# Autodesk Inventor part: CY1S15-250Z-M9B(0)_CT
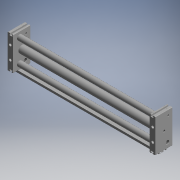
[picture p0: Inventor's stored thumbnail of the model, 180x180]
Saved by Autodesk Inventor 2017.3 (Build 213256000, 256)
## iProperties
Part Number: CY1S15-250Z-M9B(0)_CT
Material: Generic
Catalog Web Link: www.cadenas.de
Description: CY1S-Z_CT-Magnetically Coupled Rodless Cylinder Slider Type/Slide Bearing
Vendor: SMC
Document SubType Name: Modeling
Designer: partserver
Manufacturer: SMC
Mass: 219.448 g
Surface Area: 857.61 cm^2
Volume: 219.448 cm^3
Density: 1 g/cm^3
Appearance: PSOLRGB-192-192-192
Category: PARTsolutions
Company: SMC
Title: CY1S15-250Z-M9B_CT
Author: Cadenas PARTsolutions
Comments: Magnetically Coupled Rodless Cylinder Slider Type/Slide Bearing
PSOL_IDENT_0: {$CADENAS_DATA\23d-libs\smc_jp\actuator\rodless_cylinders\cy1\cy1s_z\parts\cy1s_z_cylinder_tube.prj}
PSOL_IDENT_1: ,233 {VTYP=3D},{NB=CY1S15-250Z-M9B(0)_CT},{LINA=CY1S15-250Z-M9B_CT},{NN=CY1S-Z_CT},{DATE=09.12.2020
PSOL_IDENT_2: 02:54:14},{GEOMDATE=09.03.2020 08:58:35},{VERSION=},{LINEID=30},{WBVAR=PIPING,STROKE,STOPPER,AUTOSWI
PSOL_IDENT_3: TCH,OMSC,THREAD2},{WBNUMERIC=STROKE}  {NB=CY1S15-250Z-M9B(0)_CT},{LINA=CY1S15-250Z-M9B_CT},{KT=DUMMY
PSOL_IDENT_4: },{BORE=15},{PIPING=},{STROKE=250},{STOPPER=},{AUTOSWITCH=-M9B},{OMSC=},{THREAD2=0},{STDSTROKE=50,10
PSOL_IDENT_5: 0,150,200,250,300,350,400,450,500},{SMIN=25},{SMAX=750.000},{ORDER=CY1S15-250Z-M9B},{A=7.5},{B=9.5},
PSOL_IDENT_6: {C=5.4},{D=16.6},{D1=12},{G=6.5},{GA=5.000},{GB=6},{GP=52},{H=40},{HA=28.0},{HB=29.5},{HC=20.500},{H
PSOL_IDENT_7: G=15.000},{HP=39},{HT=20.500},{JJ=M4x0.7},{JJRA=4.000},{JJRP=0.700},{JJD=5.000},{K=11.0},{L=60},{LD=
PSOL_IDENT_8: 5.8},{M=8},{MM=M5x0.8},{NA=10.5},{NB1=16.5},{NC=28.0},{NN=M4x0.7},{P=M5x0.8},{PRA=5.000},{PRP=0.800}
PSOL_IDENT_9: ,{PRD=6.000},{PA=30},{PB=50},{PW=76},{Q=75},{QW=30},{R=1.000},{R1=5.500},{S=62},{T=12.5},{TT=17.500}
PSOL_IDENT_10: ,{UU=M8x1},{UURA=8.000},{UURD=1.000},{W=72},{Y1=14.0},{Z=87},{A1=7.500},{A2=3.400},{A3=5.800},{B1=3.
PSOL_IDENT_11: 500},{B2=11.000},{B3=7.500},{B4=80.000},{J=M6x1},{JRA=6.000},{JRP=1.000},{RR=9.500},{C1=39.000},{POS=
PSOL_IDENT_12: MIN},{STOP=MIN}
NB: CY1S15-250Z-M9B(0)_CT
NN: M4x0.7
NT: Magnetically Coupled Rodless Cylinder Slider Type/Slide Bearing
NBSYN: $ORDER.($THREAD2.)_CT
LINA: CY1S15-250Z-M9B_CT
CATALOG: SMC (JP
BORE: 15
PIPING: (-) Bilateral piping type
STROKE: 250
STOPPER: (-) Bumper bolt (resin tipped):Mounted on both sides
AUTOSWITCH: M9B
OMSC: (-) None
THREAD2: on
STDSTROKE: 50,100,150,200,250,300,350,400,450,500
SMIN: 25
SMAX: 750
A: 7.5
B: 9.5
C: 5.4
D: 16.6
D1: 12
G: 6.5
GA: 5
GB: 6
GP: 52
H: 40
HA: 28
HB: 29.5
HC: 20.5
HG: 15
HP: 39
HT: 20.5
JJ: M4x0.7
JJRA: 4
JJRP: 0.7
JJD: 5
K: 11
L: 60
LD: 5.8
M: 8
MM: M5x0.8
NA: 10.5
NB1: 16.5
NC: 28
P: M5x0.8
PRA: 5
PRP: 0.8
PRD: 6
PA: 30
PB: 50
PW: 76
Q: 75
QW: 30
R: 1
R1: 5.5
S: 62
T: 12.5
TT: 17.5
UU: M8x1
UURA: 8
UURD: 1
W: 72
Y1: 14
Z: 87
A1: 7.5
A2: 3.4
A3: 5.8
B1: 3.5
B2: 11
B3: 7.5
B4: 80
J: M6x1
JRA: 6
JRP: 1
RR: 9.5
C1: 39
POS: 0
STOP: 0
SUPPLIER: SMC
ARTICLENO: CY1S15-250Z-M9B(0)_CT
BOMINFO: CY1S15-250Z-M9B_CT
CREATOR: CADENAS GmbH
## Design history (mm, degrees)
sketch "Sketch_1"
  geometry: L1 (6, -37)-(6, 37); L2 (5, 38)-(0.25, 38); L3 (0.25, 38)-(0.25, 36.1); L4 (0.25, 36.1)-(1.5, 36.1); L5 (1.5, 36.1)-(1.5, 33.4); L6 (1.5, 33.4)-(-4.5, 33.4); L7 (-4.5, 33.4)-(-4.5, 36.1); L8 (-4.5, 36.1)-(-3.25, 36.1); L9 (-3.25, 36.1)-(-3.25, 38); L10 (-3.25, 38)-(-5.5, 38); L11 (-6.5, 37)-(-6.5, -37); L12 (-5.5, -38)-(-3.25, -38); L13 (-3.25, -38)-(-3.25, -36.1); L14 (-3.25, -36.1)-(-4.5, -36.1); L15 (-4.5, -36.1)-(-4.5, -33.4); L16 (-4.5, -33.4)-(1.5, -33.4); L17 (1.5, -33.4)-(1.5, -36.1); L18 (1.5, -36.1)-(0.25, -36.1); L19 (0.25, -36.1)-(0.25, -38); L20 (0.25, -38)-(5, -38); A1 r 1 centre (5, 37) between (6, 37) and (5, 38); A2 r 1 centre (-5.5, 37) between (-5.5, 38) and (-6.5, 37); A3 r 1 centre (-5.5, -37) between (-6.5, -37) and (-5.5, -38); A4 r 1 centre (5, -37) between (5, -38) and (6, -37)
  constraints: 40 end point, 8 point on circle, 4 centre point
extrude "Extrusion1" join sketch "Sketch_1" distance "d0" = 39; taper "d1" = 0 deg
sketch "Sketch_2"
  geometry: C1 r 8.3 at (0, 20.5); 1 further point
  constraints: 1 centre point
extrude "Extrusion2" join sketch "Sketch_2" distance "d2" = 312; taper "d3" = 0 deg
sketch "Sketch_3"
  geometry: C1 r 6 at (26, 15); 1 further point
  constraints: 1 centre point
extrude "Extrusion3" join sketch "Sketch_3" distance "d4" = 312; taper "d5" = 0 deg
sketch "Sketch_4"
  geometry: C1 r 6 at (-26, 15); 1 further point
  constraints: 1 centre point
extrude "Extrusion4" join sketch "Sketch_4" distance "d6" = 312; taper "d7" = 0 deg
sketch "Sketch_5"
  geometry: L1 (-318.5, -37)-(-318.5, 37); L2 (-319.5, 38)-(-321.75, 38); L3 (-321.75, 38)-(-321.75, 36.1); L4 (-321.75, 36.1)-(-320.5, 36.1); L5 (-320.5, 36.1)-(-320.5, 33.4); L6 (-320.5, 33.4)-(-326.5, 33.4); L7 (-326.5, 33.4)-(-326.5, 36.1); L8 (-326.5, 36.1)-(-325.25, 36.1); L9 (-325.25, 36.1)-(-325.25, 38); L10 (-325.25, 38)-(-330, 38); L11 (-331, 37)-(-331, -37); L12 (-330, -38)-(-325.25, -38); L13 (-325.25, -38)-(-325.25, -36.1); L14 (-325.25, -36.1)-(-326.5, -36.1); L15 (-326.5, -36.1)-(-326.5, -33.4); L16 (-326.5, -33.4)-(-320.5, -33.4); L17 (-320.5, -33.4)-(-320.5, -36.1); L18 (-320.5, -36.1)-(-321.75, -36.1); L19 (-321.75, -36.1)-(-321.75, -38); L20 (-321.75, -38)-(-319.5, -38); A1 r 1 centre (-319.5, 37) between (-318.5, 37) and (-319.5, 38); A2 r 1 centre (-330, 37) between (-330, 38) and (-331, 37); A3 r 1 centre (-330, -37) between (-331, -37) and (-330, -38); A4 r 1 centre (-319.5, -37) between (-319.5, -38) and (-318.5, -37)
  constraints: 40 end point, 8 point on circle, 4 centre point
extrude "Extrusion5" join sketch "Sketch_5" distance "d8" = 39; taper "d9" = 0 deg
sketch "Sketch_45"
  geometry: L1 (-39.8, 41)-(-39.8, 9); L2 (-39.8, 9)-(-37.8, 11); L3 (-37.8, 11)-(-37.8, 30); L4 (-37.8, 30)-(-38, 30.2); L5 (-38, 30.2)-(-38, 39); L6 (-38, 39)-(38, 39); L7 (38, 39)-(38, 30.2); L8 (38, 30.2)-(37.8, 30); L9 (37.8, 30)-(37.8, 11); L10 (37.8, 11)-(39.8, 9); L11 (39.8, 9)-(39.8, 41); L12 (39.8, 41)-(-39.8, 41)
  constraints: 24 end point
extrude "Extrusion6" cut sketch "Sketch_45" distance "d10" = 353.5; taper "d11" = 0 deg
sketch "Sketch7"
  geometry: 1 further point
hole "Hole1" sketch "Sketch7" at (0, -15) diameter "d12" = 5.8; stored, may be unused: countersink angle "d16" = 90 deg, drill point angle "d18" = 0 deg; dims "d13" = 6, "d14" = 9.5, "d15" = 5.4, "d17" = 39
pattern_linear "Rectangular Pattern1" dims "d21" = 325, "d24" = 30
sketch "Sketch_8"
  geometry: L1 (-6, 29.5)-(6.5, 29.5); L2 (6.5, 29.5)-(6.5, 27.5); L3 (6.5, 27.5)-(6.121, 27.879); L4 (6.121, 27.879)-(-5.621, 27.879); L5 (-5.621, 27.879)-(-6, 27.5); L6 (-6, 27.5)-(-6, 29.5); L7 (-6, 29.5)-(6.5, 29.5)
  constraints: 14 end point
revolve "Revolution1" sketch "Sketch_8" stored, may be unused: angle "d25" = 360 deg
thread "Thread1" dims "d26" = 11.742, "d27" = 0
sketch "Sketch_9"
  geometry: L1 (318.5, 29.5)-(331, 29.5); L2 (331, 29.5)-(331, 27.5); L3 (331, 27.5)-(330.621, 27.879); L4 (330.621, 27.879)-(318.879, 27.879); L5 (318.879, 27.879)-(318.5, 27.5); L6 (318.5, 27.5)-(318.5, 29.5); L7 (318.5, 29.5)-(331, 29.5)
  constraints: 14 end point
revolve "Revolution2" sketch "Sketch_9" stored, may be unused: angle "d28" = 360 deg
thread "Thread2" dims "d29" = 11.742, "d30" = 0
sketch "Sketch_12"
  geometry: L1 (-6, 28)-(6.5, 28); L2 (6.5, 28)-(6.5, 24); L3 (6.5, 24)-(5.958, 24.542); L4 (5.958, 24.542)-(-5.459, 24.542); L5 (-5.459, 24.542)-(-6, 24); L6 (-6, 24)-(-6, 28); L7 (-6, 28)-(6.5, 28)
  constraints: 14 end point
revolve "Revolution3" sketch "Sketch_12" stored, may be unused: angle "d31" = 360 deg
thread "Thread3" dims "d32" = 11.417, "d33" = 0
sketch "Sketch_13"
  geometry: L1 (318.5, 28)-(331, 28); L2 (331, 28)-(331, 24); L3 (331, 24)-(330.459, 24.542); L4 (330.459, 24.542)-(319.042, 24.542); L5 (319.042, 24.542)-(318.5, 24); L6 (318.5, 24)-(318.5, 28); L7 (318.5, 28)-(331, 28)
  constraints: 14 end point
revolve "Revolution4" sketch "Sketch_13" stored, may be unused: angle "d34" = 360 deg
thread "Thread4" dims "d35" = 11.417, "d36" = 0
sketch "Sketch_16"
  geometry: L1 (1.193, 20.5)-(-6, 20.5); L2 (-6, 20.5)-(-6, 23); L3 (-6, 23)-(-5.567, 22.567); L4 (-5.567, 22.567)-(0, 22.567); L5 (0, 22.567)-(1.193, 20.5); L6 (1.193, 20.5)-(-6, 20.5)
  constraints: 12 end point
revolve "Revolution5" sketch "Sketch_16" stored, may be unused: angle "d37" = 360 deg
thread "Thread5" dims "d38" = 5.567, "d39" = 0
sketch "Sketch_17"
  geometry: L1 (331, 20.5)-(323.807, 20.5); L2 (323.807, 20.5)-(325, 22.567); L3 (325, 22.567)-(330.567, 22.567); L4 (330.567, 22.567)-(331, 23); L5 (331, 23)-(331, 20.5); L6 (331, 20.5)-(323.807, 20.5)
  constraints: 12 end point
revolve "Revolution6" sketch "Sketch_17" stored, may be unused: angle "d40" = 360 deg
thread "Thread6" dims "d41" = 5.567, "d42" = 0
sketch "Sketch_22"
  geometry: L1 (1.5, -41.9)-(1.5, -33.7); L2 (1.5, -33.7)-(4.25, -33.7); L3 (4.25, -33.7)-(4.25, -36.1); L4 (4.25, -36.1)-(3, -36.1); L5 (3, -36.1)-(3, -39.2); L6 (3, -39.2)-(4.45, -39.2); L7 (4.45, -39.2)-(4.45, -39.9); L8 (4.45, -39.9)-(4.25, -39.9); L9 (4.25, -39.9)-(4.25, -40.9); L10 (3.25, -41.9)-(1.5, -41.9); L11 (1.5, -41.9)-(1.5, -33.7); A1 r 1 centre (3.25, -40.9) between (3.25, -41.9) and (4.25, -40.9)
  constraints: 22 end point, 2 point on circle, 1 centre point
revolve "Revolution7" sketch "Sketch_22" stored, may be unused: angle "d43" = 360 deg
sketch "Sketch_24"
  geometry: L1 (323.5, -41.9)-(323.5, -33.7); L2 (323.5, -33.7)-(326.25, -33.7); L3 (326.25, -33.7)-(326.25, -36.1); L4 (326.25, -36.1)-(325, -36.1); L5 (325, -36.1)-(325, -39.2); L6 (325, -39.2)-(326.45, -39.2); L7 (326.45, -39.2)-(326.45, -39.9); L8 (326.45, -39.9)-(326.25, -39.9); L9 (326.25, -39.9)-(326.25, -40.9); L10 (325.25, -41.9)-(323.5, -41.9); L11 (323.5, -41.9)-(323.5, -33.7); A1 r 1 centre (325.25, -40.9) between (325.25, -41.9) and (326.25, -40.9)
  constraints: 22 end point, 2 point on circle, 1 centre point
revolve "Revolution8" sketch "Sketch_24" stored, may be unused: angle "d44" = 360 deg
sketch "Sketch_23"
  geometry: L1 (-43.4, 28.5)-(-43.4, 27.5); L2 (-43.4, 27.5)-(-42.658, 27.5); L3 (-38.8, 27.04)-(-38.8, 22.96); L4 (-42.658, 22.5)-(-43.4, 22.5); L5 (-43.4, 22.5)-(-43.4, 18.8); L6 (-43.1, 18.5)-(-42.6, 18.5); L7 (-42.3, 18.8)-(-42.3, 19.5); L8 (-41.3, 20.5)-(-39.5, 20.5); L9 (-39.2, 20.2)-(-39.2, 13.3); L10 (-39.5, 13)-(-41.3, 13); L11 (-42.3, 14)-(-42.3, 15.2); L12 (-42.6, 15.5)-(-43.1, 15.5); L13 (-43.4, 15.2)-(-43.4, 12); L14 (-42.4, 11)-(-37.8, 11); L15 (-37.8, 11)-(-37.8, 29.5); L16 (-37.8, 29.5)-(-42.4, 29.5); A1 r 3 centre (-41, 25) between (-38.8, 27.04) and (-42.658, 27.5); A2 r 3 centre (-41, 25) between (-42.658, 22.5) and (-38.8, 22.96); A3 r 0.3 centre (-43.1, 18.8) between (-43.4, 18.8) and (-43.1, 18.5); A4 r 0.3 centre (-42.6, 18.8) between (-42.6, 18.5) and (-42.3, 18.8); A5 r 1 centre (-41.3, 19.5) between (-41.3, 20.5) and (-42.3, 19.5); A6 r 0.3 centre (-39.5, 20.2) between (-39.2, 20.2) and (-39.5, 20.5); A7 r 0.3 centre (-39.5, 13.3) between (-39.5, 13) and (-39.2, 13.3); A8 r 1 centre (-41.3, 14) between (-42.3, 14) and (-41.3, 13); A9 r 0.3 centre (-42.6, 15.2) between (-42.3, 15.2) and (-42.6, 15.5); A10 r 0.3 centre (-43.1, 15.2) between (-43.1, 15.5) and (-43.4, 15.2); A11 r 1 centre (-42.4, 12) between (-43.4, 12) and (-42.4, 11); A12 r 1 centre (-42.4, 28.5) between (-42.4, 29.5) and (-43.4, 28.5)
  constraints: 32 end point, 24 point on circle, 12 centre point
extrude "Extrusion7" join sketch "Sketch_23" distance "d45" = 330; taper "d46" = 0 deg
node "CT_BODY_XY"
node "CT_BODY_YZ"
node "CT_BODY_ZX"
node "CT_BODY_X"
node "CT_BODY_Y"
node "CT_BODY_Z"
node "CT_BODY_Center"
node "CT_DUMMY_XY"
node "CT_DUMMY_YZ"
node "CT_DUMMY_ZX"
node "CT_DUMMY_X"
node "CT_DUMMY_Y"
node "CT_DUMMY_Z"
node "CT_DUMMY_Center"
node "CT_SMA1_XY"
node "CT_SMA1_YZ"
node "CT_SMA1_ZX"
node "CT_SMA1_X"
node "CT_SMA1_Y"
node "CT_SMA1_Z"
node "CT_SMA1_Center"
node "CT_SMA2_XY"
node "CT_SMA2_YZ"
node "CT_SMA2_ZX"
node "CT_SMA2_X"
node "CT_SMA2_Y"
node "CT_SMA2_Z"
node "CT_SMA2_Center"
node "CT_SMB1_XY"
node "CT_SMB1_YZ"
node "CT_SMB1_ZX"
node "CT_SMB1_X"
node "CT_SMB1_Y"
node "CT_SMB1_Z"
node "CT_SMB1_Center"
node "CT_STOPPER1_XY"
node "CT_STOPPER1_YZ"
node "CT_STOPPER1_ZX"
node "CT_STOPPER1_X"
node "CT_STOPPER1_Y"
node "CT_STOPPER1_Z"
node "CT_STOPPER1_Center"
node "CT_STOPPER2_XY"
node "CT_STOPPER2_YZ"
node "CT_STOPPER2_ZX"
node "CT_STOPPER2_X"
node "CT_STOPPER2_Y"
node "CT_STOPPER2_Z"
node "CT_STOPPER2_Center"
node "CT_STOPPER3_XY"
node "CT_STOPPER3_YZ"
node "CT_STOPPER3_ZX"
node "CT_STOPPER3_X"
node "CT_STOPPER3_Y"
node "CT_STOPPER3_Z"
node "CT_STOPPER3_Center"
node "CT_STOPPER4_XY"
node "CT_STOPPER4_YZ"
node "CT_STOPPER4_ZX"
node "CT_STOPPER4_X"
node "CT_STOPPER4_Y"
node "CT_STOPPER4_Z"
node "CT_STOPPER4_Center"
body "Solid1"
other parameters: "d47" = 0, "d48" = 0, "d49" = 0, "d50" = 0
